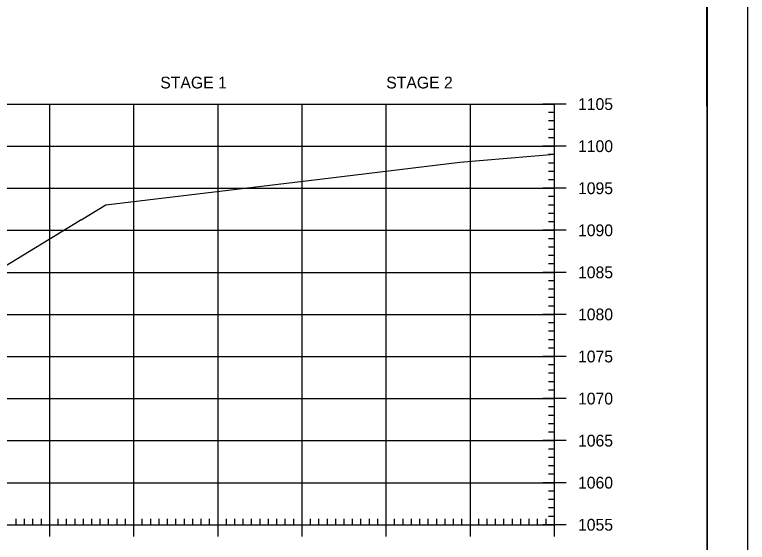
# Model space of a CAD drawing. Extents: x 1322838 to 1324533, y 339903 to 351025.
# Drawn here: x 1323779.5 to 1323866.6, y 344121 to 344183.7 of the extents above; entities that cross this region are included whole.
import ezdxf

# ---------------------------------------------------------------- set-up
doc = ezdxf.new("R2010")
doc.units = 0
for name, color, linetype in [('R_Axis', 7, 'Continuous'), ('R_Axis Annot', 7, 'Continuous'), ('R_Border', 7, 'Continuous'), ('R_Exist Surface', 7, 'Continuous'), ('R_Grid', 7, 'Continuous'), ('R_No Plot', 7, 'Continuous')]:
    doc.layers.add(name, color=color, linetype=linetype)

msp = doc.modelspace()

# ---------------------------------------------------------------- linework, layer by layer
at = {"layer": 'R_Axis'}
for p, q in [((1323845.115, 344173.057), (1323842.315, 344173.057)), ((1323843.715, 344123.057), (1323843.715, 344173.057)), ((1323843.715, 344172.057), (1323843.015, 344172.057)), ((1323843.715, 344171.057), (1323843.015, 344171.057)), ((1323843.715, 344170.057), (1323843.015, 344170.057)), ((1323843.715, 344169.057), (1323843.015, 344169.057)), ((1323845.115, 344168.057), (1323842.315, 344168.057)), ((1323843.715, 344167.057), (1323843.015, 344167.057)), ((1323843.715, 344166.057), (1323843.015, 344166.057)), ((1323843.715, 344165.057), (1323843.015, 344165.057)), ((1323843.715, 344164.057), (1323843.015, 344164.057)), ((1323845.115, 344163.057), (1323842.315, 344163.057)), ((1323843.715, 344162.057), (1323843.015, 344162.057)), ((1323843.715, 344161.057), (1323843.015, 344161.057)), ((1323843.715, 344160.057), (1323843.015, 344160.057)), ((1323843.715, 344159.057), (1323843.015, 344159.057)), ((1323845.115, 344158.057), (1323842.315, 344158.057)), ((1323843.715, 344157.057), (1323843.015, 344157.057)), ((1323843.715, 344156.057), (1323843.015, 344156.057)), ((1323843.715, 344155.057), (1323843.015, 344155.057)), ((1323843.715, 344154.057), (1323843.015, 344154.057)), ((1323845.115, 344153.057), (1323842.315, 344153.057)), ((1323843.715, 344152.057), (1323843.015, 344152.057)), ((1323843.715, 344151.057), (1323843.015, 344151.057)), ((1323843.715, 344150.057), (1323843.015, 344150.057)), ((1323843.715, 344149.057), (1323843.015, 344149.057)), ((1323845.115, 344148.057), (1323842.315, 344148.057)), ((1323843.715, 344147.057), (1323843.015, 344147.057)), ((1323843.715, 344146.057), (1323843.015, 344146.057)), ((1323843.715, 344145.057), (1323843.015, 344145.057)), ((1323843.715, 344144.057), (1323843.015, 344144.057)), ((1323845.115, 344143.057), (1323842.315, 344143.057)), ((1323843.715, 344142.057), (1323843.015, 344142.057)), ((1323843.715, 344141.057), (1323843.015, 344141.057)), ((1323843.715, 344140.057), (1323843.015, 344140.057)), ((1323843.715, 344139.057), (1323843.015, 344139.057)), ((1323845.115, 344138.057), (1323842.315, 344138.057)), ((1323843.715, 344137.057), (1323843.015, 344137.057)), ((1323843.715, 344136.057), (1323843.015, 344136.057)), ((1323843.715, 344135.057), (1323843.015, 344135.057)), ((1323843.715, 344134.057), (1323843.015, 344134.057)), ((1323845.115, 344133.057), (1323842.315, 344133.057)), ((1323843.715, 344132.057), (1323843.015, 344132.057)), ((1323843.715, 344131.057), (1323843.015, 344131.057)), ((1323843.715, 344130.057), (1323843.015, 344130.057)), ((1323843.715, 344129.057), (1323843.015, 344129.057)), ((1323845.115, 344128.057), (1323842.315, 344128.057)), ((1323843.715, 344127.057), (1323843.015, 344127.057)), ((1323843.715, 344126.057), (1323843.015, 344126.057)), ((1323843.715, 344125.057), (1323843.015, 344125.057)), ((1323779.715, 344123.057), (1323779.715, 344123.757)), ((1323780.715, 344123.057), (1323780.715, 344123.757)), ((1323781.715, 344123.057), (1323781.715, 344123.757)), ((1323782.715, 344123.057), (1323782.715, 344123.757)), ((1323783.715, 344121.657), (1323783.715, 344124.457)), ((1323784.715, 344123.057), (1323784.715, 344123.757)), ((1323785.715, 344123.057), (1323785.715, 344123.757)), ((1323786.715, 344123.057), (1323786.715, 344123.757)), ((1323787.715, 344123.057), (1323787.715, 344123.757)), ((1323788.715, 344123.057), (1323788.715, 344123.757)), ((1323789.715, 344123.057), (1323789.715, 344123.757)), ((1323790.715, 344123.057), (1323790.715, 344123.757)), ((1323791.715, 344123.057), (1323791.715, 344123.757)), ((1323792.715, 344123.057), (1323792.715, 344123.757)), ((1323793.715, 344121.657), (1323793.715, 344124.457)), ((1323794.715, 344123.057), (1323794.715, 344123.757)), ((1323795.715, 344123.057), (1323795.715, 344123.757)), ((1323796.715, 344123.057), (1323796.715, 344123.757)), ((1323797.715, 344123.057), (1323797.715, 344123.757)), ((1323798.715, 344123.057), (1323798.715, 344123.757)), ((1323799.715, 344123.057), (1323799.715, 344123.757)), ((1323800.715, 344123.057), (1323800.715, 344123.757)), ((1323801.715, 344123.057), (1323801.715, 344123.757)), ((1323802.715, 344123.057), (1323802.715, 344123.757)), ((1323803.715, 344121.657), (1323803.715, 344124.457)), ((1323804.715, 344123.057), (1323804.715, 344123.757)), ((1323805.715, 344123.057), (1323805.715, 344123.757)), ((1323806.715, 344123.057), (1323806.715, 344123.757)), ((1323807.715, 344123.057), (1323807.715, 344123.757)), ((1323808.715, 344123.057), (1323808.715, 344123.757)), ((1323809.715, 344123.057), (1323809.715, 344123.757)), ((1323810.715, 344123.057), (1323810.715, 344123.757)), ((1323811.715, 344123.057), (1323811.715, 344123.757)), ((1323812.715, 344123.057), (1323812.715, 344123.757)), ((1323813.715, 344121.657), (1323813.715, 344124.457)), ((1323814.715, 344123.057), (1323814.715, 344123.757)), ((1323815.715, 344123.057), (1323815.715, 344123.757)), ((1323816.715, 344123.057), (1323816.715, 344123.757)), ((1323817.715, 344123.057), (1323817.715, 344123.757)), ((1323818.715, 344123.057), (1323818.715, 344123.757)), ((1323819.715, 344123.057), (1323819.715, 344123.757)), ((1323820.715, 344123.057), (1323820.715, 344123.757)), ((1323821.715, 344123.057), (1323821.715, 344123.757)), ((1323822.715, 344123.057), (1323822.715, 344123.757)), ((1323823.715, 344121.657), (1323823.715, 344124.457)), ((1323824.715, 344123.057), (1323824.715, 344123.757)), ((1323825.715, 344123.057), (1323825.715, 344123.757)), ((1323826.715, 344123.057), (1323826.715, 344123.757)), ((1323827.715, 344123.057), (1323827.715, 344123.757)), ((1323828.715, 344123.057), (1323828.715, 344123.757)), ((1323829.715, 344123.057), (1323829.715, 344123.757)), ((1323830.715, 344123.057), (1323830.715, 344123.757)), ((1323831.715, 344123.057), (1323831.715, 344123.757)), ((1323832.715, 344123.057), (1323832.715, 344123.757)), ((1323833.715, 344121.657), (1323833.715, 344124.457)), ((1323834.715, 344123.057), (1323834.715, 344123.757)), ((1323835.715, 344123.057), (1323835.715, 344123.757)), ((1323836.715, 344123.057), (1323836.715, 344123.757)), ((1323837.715, 344123.057), (1323837.715, 344123.757)), ((1323838.715, 344123.057), (1323838.715, 344123.757)), ((1323839.715, 344123.057), (1323839.715, 344123.757)), ((1323840.715, 344123.057), (1323840.715, 344123.757)), ((1323841.715, 344123.057), (1323841.715, 344123.757)), ((1323842.715, 344123.057), (1323842.715, 344123.757)), ((1323843.715, 344124.057), (1323843.015, 344124.057)), ((1323843.715, 344121.657), (1323843.715, 344124.457)), ((1323563.715, 344123.057), (1323843.715, 344123.057)), ((1323845.115, 344123.057), (1323842.315, 344123.057))]:
    msp.add_line(p, q, dxfattribs=at)
at = {"layer": 'R_Border'}
msp.add_line((1323861.895, 344037.057), (1323861.895, 344242.517), dxfattribs=at)
at = {"layer": 'R_Exist Surface'}
msp.add_lwpolyline([(1323777.698, 344153.397), (1323787.202, 344159.183), (1323787.386, 344159.29), (1323787.435, 344159.319), (1323790.375, 344161.067), (1323815.824, 344164.142), (1323832.485, 344166.154), (1323843.715, 344167.114)], dxfattribs=at)
at = {"layer": 'R_Grid'}
for p, q in [((1323563.715, 344173.057), (1323843.715, 344173.057)), ((1323783.715, 344123.057), (1323783.715, 344173.057)), ((1323793.715, 344123.057), (1323793.715, 344173.057)), ((1323803.715, 344123.057), (1323803.715, 344173.057)), ((1323813.715, 344123.057), (1323813.715, 344173.057)), ((1323823.715, 344123.057), (1323823.715, 344173.057)), ((1323833.715, 344123.057), (1323833.715, 344173.057)), ((1323843.715, 344123.057), (1323843.715, 344173.057)), ((1323563.715, 344168.057), (1323843.715, 344168.057)), ((1323563.715, 344163.057), (1323843.715, 344163.057)), ((1323563.715, 344158.057), (1323843.715, 344158.057)), ((1323563.715, 344153.057), (1323843.715, 344153.057)), ((1323563.715, 344148.057), (1323843.715, 344148.057)), ((1323563.715, 344143.057), (1323843.715, 344143.057)), ((1323563.715, 344138.057), (1323843.715, 344138.057)), ((1323563.715, 344133.057), (1323843.715, 344133.057)), ((1323563.715, 344128.057), (1323843.715, 344128.057)), ((1323563.715, 344123.057), (1323843.715, 344123.057))]:
    msp.add_line(p, q, dxfattribs=at)
at = {"layer": 'R_No Plot'}
for points in [[(1323533.308, 344246.412), (1323866.648, 344246.412), (1323866.648, 344033.074), (1323533.308, 344033.074)], [(1323779.635, 344242.517), (1323799.255, 344242.517), (1323799.255, 344232.637), (1323815.368, 344232.637), (1323838.567, 344232.637), (1323838.567, 344199.967), (1323861.775, 344199.967), (1323861.895, 344037.057), (1323545.715, 344037.057), (1323545.715, 344242.517)]]:
    msp.add_lwpolyline(points, close=True, dxfattribs=at)

# ---------------------------------------------------------------- texts
at = {"layer": 'R_Axis Annot'}
for s, p in [('STAGE 1', (1323796.852, 344174.918)), ('STAGE 2', (1323823.715, 344174.918)), ('1105', (1323846.515, 344172.357)), ('1100', (1323846.515, 344167.357)), ('1095', (1323846.515, 344162.357)), ('1090', (1323846.515, 344157.357)), ('1085', (1323846.515, 344152.357)), ('1080', (1323846.515, 344147.357)), ('1075', (1323846.515, 344142.357)), ('1070', (1323846.515, 344137.357)), ('1065', (1323846.515, 344132.357)), ('1060', (1323846.515, 344127.357)), ('1055', (1323846.515, 344122.357))]:
    msp.add_text(s, height=1.4, dxfattribs=at).set_placement(p)

doc.saveas('drawing.dxf')
